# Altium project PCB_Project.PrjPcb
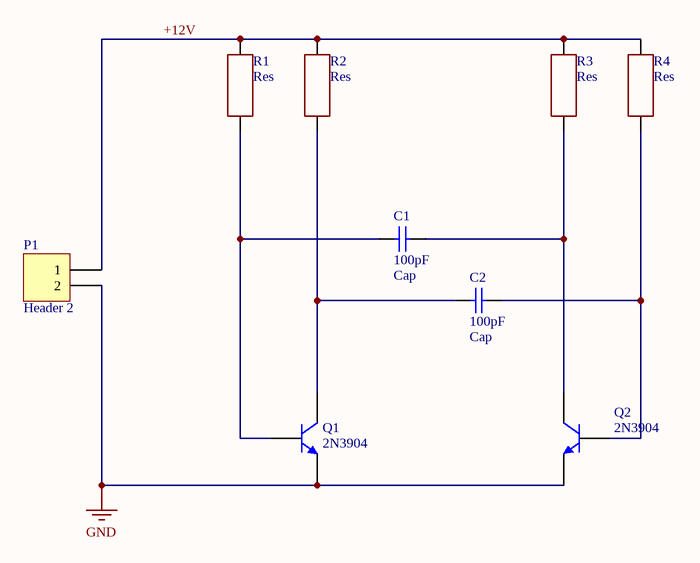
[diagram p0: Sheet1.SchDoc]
1 sheet, 9 parts. Net scope: global (net labels, ports and power ports of the same name join across sheets).
Board file: PCB1.PcbDoc

## Sheet Sheet1.SchDoc
size A4; SheetNumber: 1; SheetTotal: 1; SPICEModelCacheJFKDNKES: <root> / <DocumentId>JFKDNKES</DocumentId> / <CacheFrame Number="0"> / <Model Name="2n3904" Kind="MDL"> / <Text>*2N3904 / *Si 310mW  40V 200mA 300MHz pkg:TO-92B 1,2,3 / .MODEL 2N3904 NPN(IS=1.4E-14 BF=300 VAF=100 IKF=0.025 ISE=3E-13 / + BR=7.5 RC=2.4 CJE=4.5E-12 TF=4E-10 CJC=3.5E-12 TR=2.1E-8 XTB=1.5 KF=9E-16 )</Text> / </Model> / </CacheFrame> / </root>

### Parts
C1  Cap  value 100pF  [RAD-0.3]
C2  Cap  value 100pF  [RAD-0.3]
P1  Header 2  [HDR1X2]
Q1  2N3904  [TO-92A]
Q2  2N3904  [TO-92A]
R1  Res  [Res 0805]
R2  Res  [Res 0805]
R3  Res  [Res 0805]
R4  Res  [Res 0805]

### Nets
GND: P1.2 Q1.1(E) Q2.1(E)
+12V: P1.1 R1.2 R2.2 R3.2 R4.2
NetC1_1: C1.1 Q1.2(B) R1.1
NetC1_2: C1.2 Q2.3(C) R3.1
NetC2_1: C2.1 Q1.3(C) R2.1
NetC2_2: C2.2 Q2.2(B) R4.1

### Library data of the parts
C1 C2 = Cap: Capacitor
P1 = Header 2: Header, 2-Pin
Q1 Q2 = 2N3904: NPN General Purpose Amplifier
